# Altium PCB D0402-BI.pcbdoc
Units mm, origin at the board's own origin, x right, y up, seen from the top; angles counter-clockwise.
Board outline 15.05 x 13.71 mm, 2 copper layers (Top Layer, Bottom Layer), stack 0 mm thick; 1 components, 0 nets, 2 pads, 0 vias.
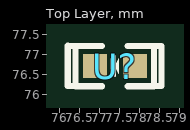
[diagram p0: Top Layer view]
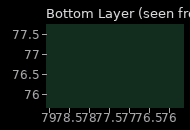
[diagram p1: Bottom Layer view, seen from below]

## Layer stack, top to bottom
Top Layer: signal copper (thickness not stored)
Bottom Layer: signal copper (thickness not stored)

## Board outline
84.898,69.85 69.85,69.85 69.85,83.562 84.898,83.562

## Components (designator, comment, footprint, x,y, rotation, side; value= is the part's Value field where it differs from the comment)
U? "" D0402-BI 77.378,76.704 r0 top

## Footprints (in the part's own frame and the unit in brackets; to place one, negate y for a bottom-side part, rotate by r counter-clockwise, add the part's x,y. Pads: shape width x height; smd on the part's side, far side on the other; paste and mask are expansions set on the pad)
D0402-BI [mm]
  rect 0.6x0.6 smd paste-100 mask+0.051: 1(-0.5,0) 2(0.5,0)
  silkscreen extent -1.18,-0.5 1.17,0.51

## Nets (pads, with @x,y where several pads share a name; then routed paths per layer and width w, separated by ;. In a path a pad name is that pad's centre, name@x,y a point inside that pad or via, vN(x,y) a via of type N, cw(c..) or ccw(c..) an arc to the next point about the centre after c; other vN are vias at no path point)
pads on no net: U?.1 U?.2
